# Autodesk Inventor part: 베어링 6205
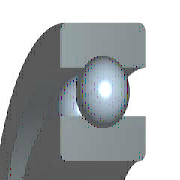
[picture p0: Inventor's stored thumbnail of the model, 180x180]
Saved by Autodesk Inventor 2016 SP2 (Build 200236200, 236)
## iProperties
Created: 2015-10
Part Number: 베어링 6205
Material: 강, 연강
Description: 깊은 그루브 볼 베어링
Document SubType Name: Modeling
Standard: KS B 2023
Designer: mdu
Standards Organization: KS
Language: ko-KR
Size Designation: 6205 - 25 x 52 x 15
Categories: <MemberInstance><Categories><Category DisplayName="샤프트 부품" InternalName="7f7aeb1f-a693-4053-b835-cee3144e0d98" Mnemonic="SHFT"><Category DisplayName="베어링" Inter
Density: 7.86 g/cm^3
Appearance: 노란색
Mass: 129.543 g
Surface Area: 107.326 cm^2
Volume: 16.4813 cm^3
IsCustomPart: 1
Author: mdu
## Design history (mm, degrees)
sketch "스케치" dims "d0" = 7.02 (= -0.26 x WD + 0.26 x BD)
  geometry: L1 (3.99, 19.25)-(11.01, 19.25); L2 (7.5, 19.25)-(7.5, 15.74); L3 (7.5, 19.25)-(7.5, 22.76); L4 (4.892, 16.901)-(0, 16.901); L5 (0, 12.5)-(15, 12.5); L6 (4.892, 21.599)-(0, 21.599); L7 (0, 26)-(15, 26); L8 (15, 12.5)-(15, 16.901); L9 (10.108, 16.901)-(15, 16.901); L10 (10.108, 21.599)-(15, 21.599); L11 (15, 26)-(15, 21.599); L12 (-1.4, 0)-(8.4, 0) reference; L13 (0, -0.3)-(0, 5.3) reference
  constraints: 22 end point, 4 point on line, 2 collinear, 2 perpendicular, 2 symmetric about line, 1 midpoint, 1 parallel, 14 other
  dimensions: "d9" = 25 diameter of L5 L12 (= WD); "d11" = 52 diameter of L7 L12 (= BD); "d12" = 15 distance between parallel lines of L8 L13 (= KB); "d13" = 33.802 diameter of L9 L12 (= 0.326 x BD + 0.674 x WD)
revolve "본체" stored, may be unused: angle "d6" = 90 deg
revolve "볼" stored, may be unused: angle "d7" = 90 deg
pattern_circular "IDS_ARRAYBALL[SIMPL:T]" dims angle "d3" = 360 deg
body "Solid1"
fillet "모깎기1" dims "d1" = 1 (= KRS)
other parameters: "WD" = 25 [user parameter; used in 5 equation terms], "BD" = 52 [user parameter; used in 5 equation terms], "KB" = 15 [user parameter; used in 1 equation term], "KRS" = 1 [user parameter; used in 1 equation term], "d4" = 0, "d5" = 0, "d8" = 0, "d14" = 0, "d15" = 0, "BBA" = 0 [user parameter], "BC0" = 7800000 [user parameter], "BC" = 1.4e+07 [user parameter], "BR" = 26 (= 0.5 x BD) [user parameter], "WR" = 12.5 (= 0.5 x WD) [user parameter]
